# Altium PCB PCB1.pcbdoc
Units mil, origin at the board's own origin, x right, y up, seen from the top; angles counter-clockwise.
Board outline 2191.35 x 1279.37 mil, 4 copper layers (Top Layer, Inner1, Inner2, Bottom Layer), stack 38.584 mil thick; 62 components, 47 nets, 215 pads, 120 vias.
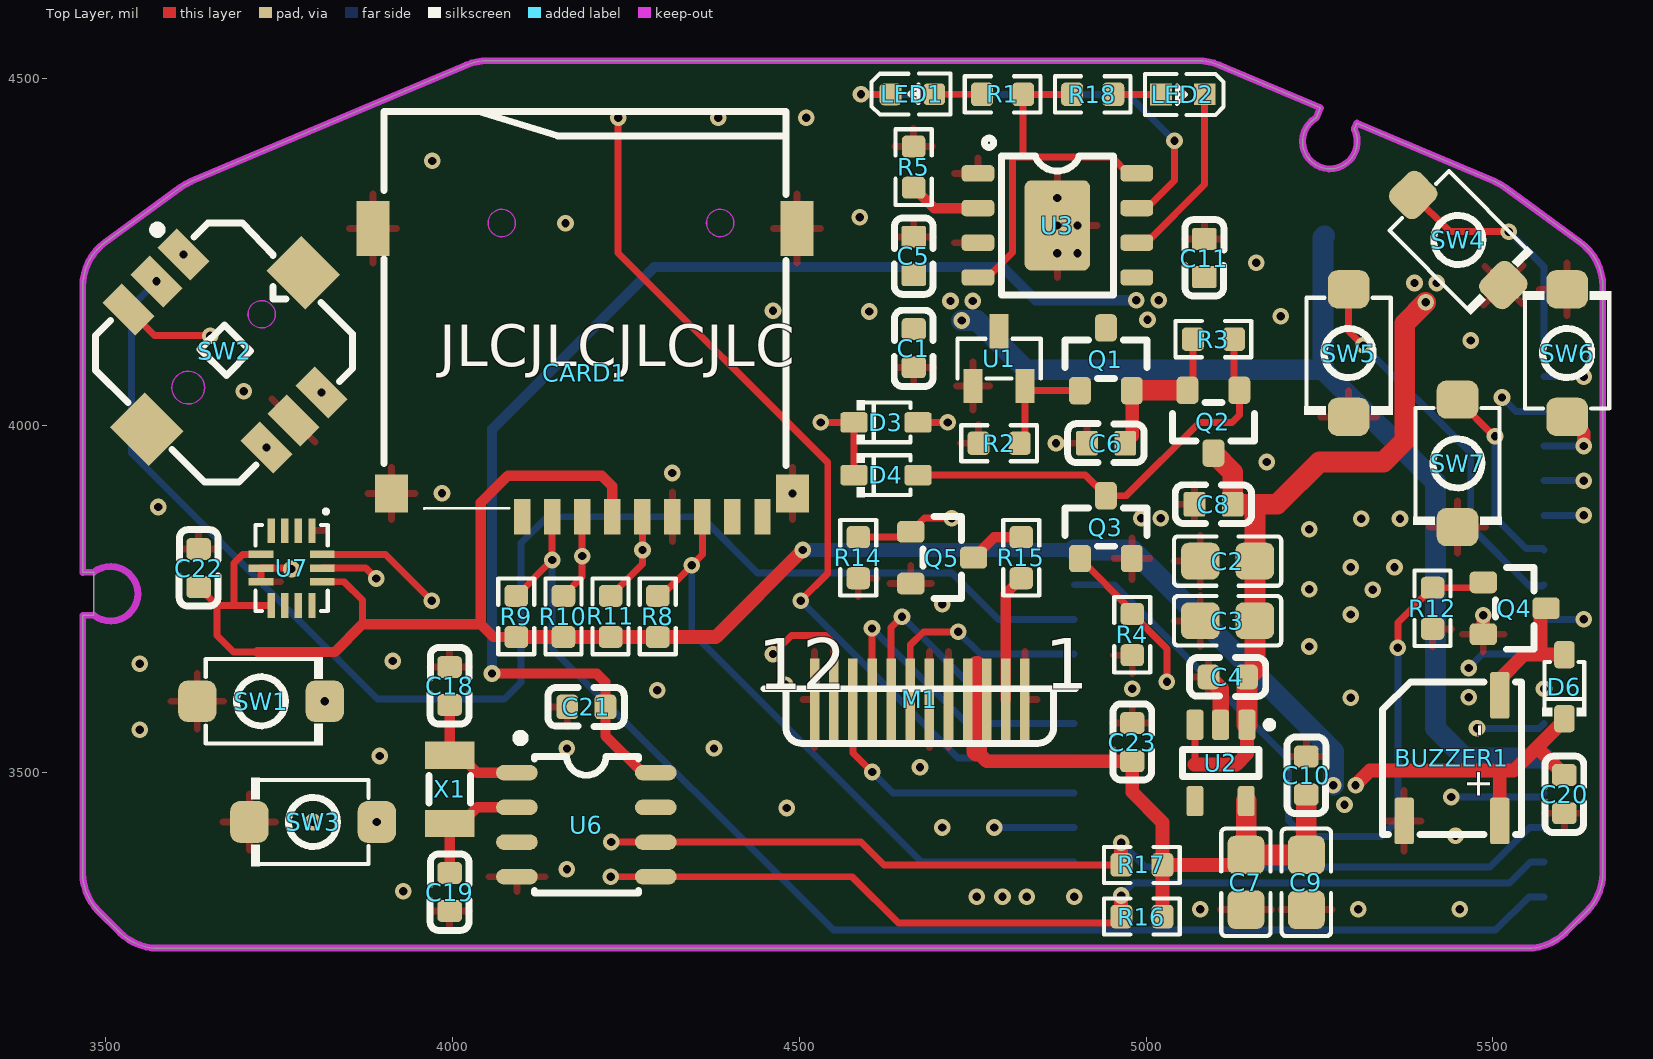
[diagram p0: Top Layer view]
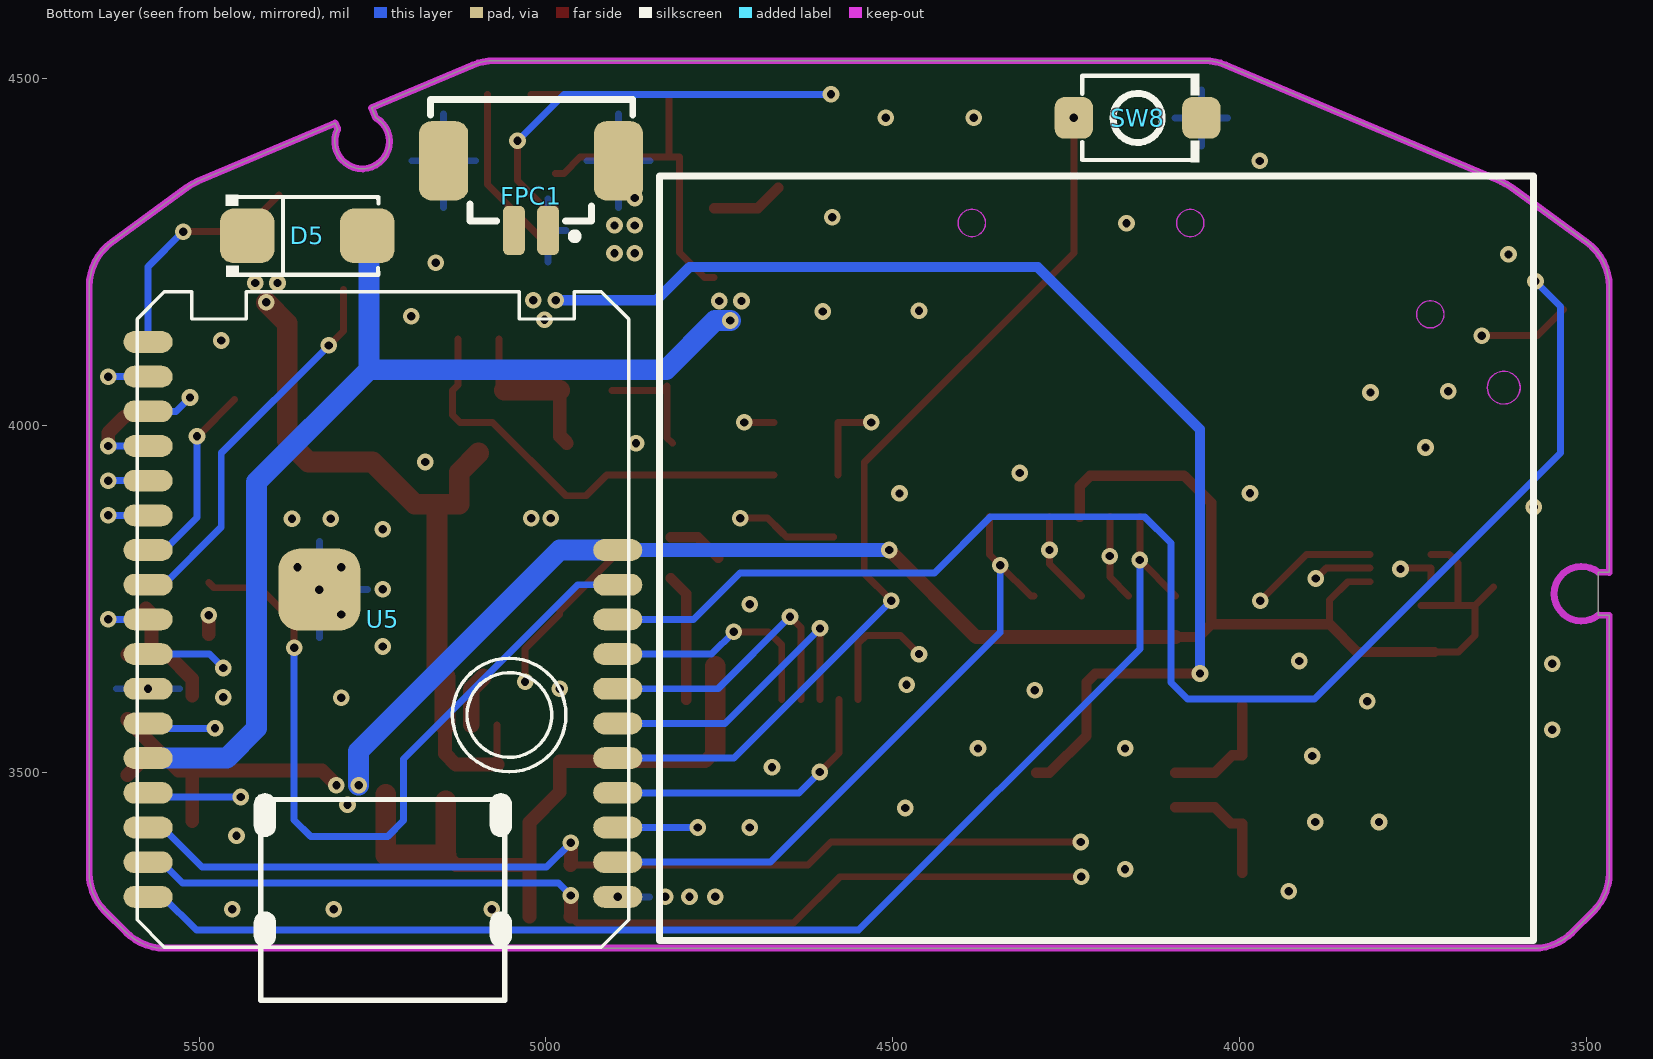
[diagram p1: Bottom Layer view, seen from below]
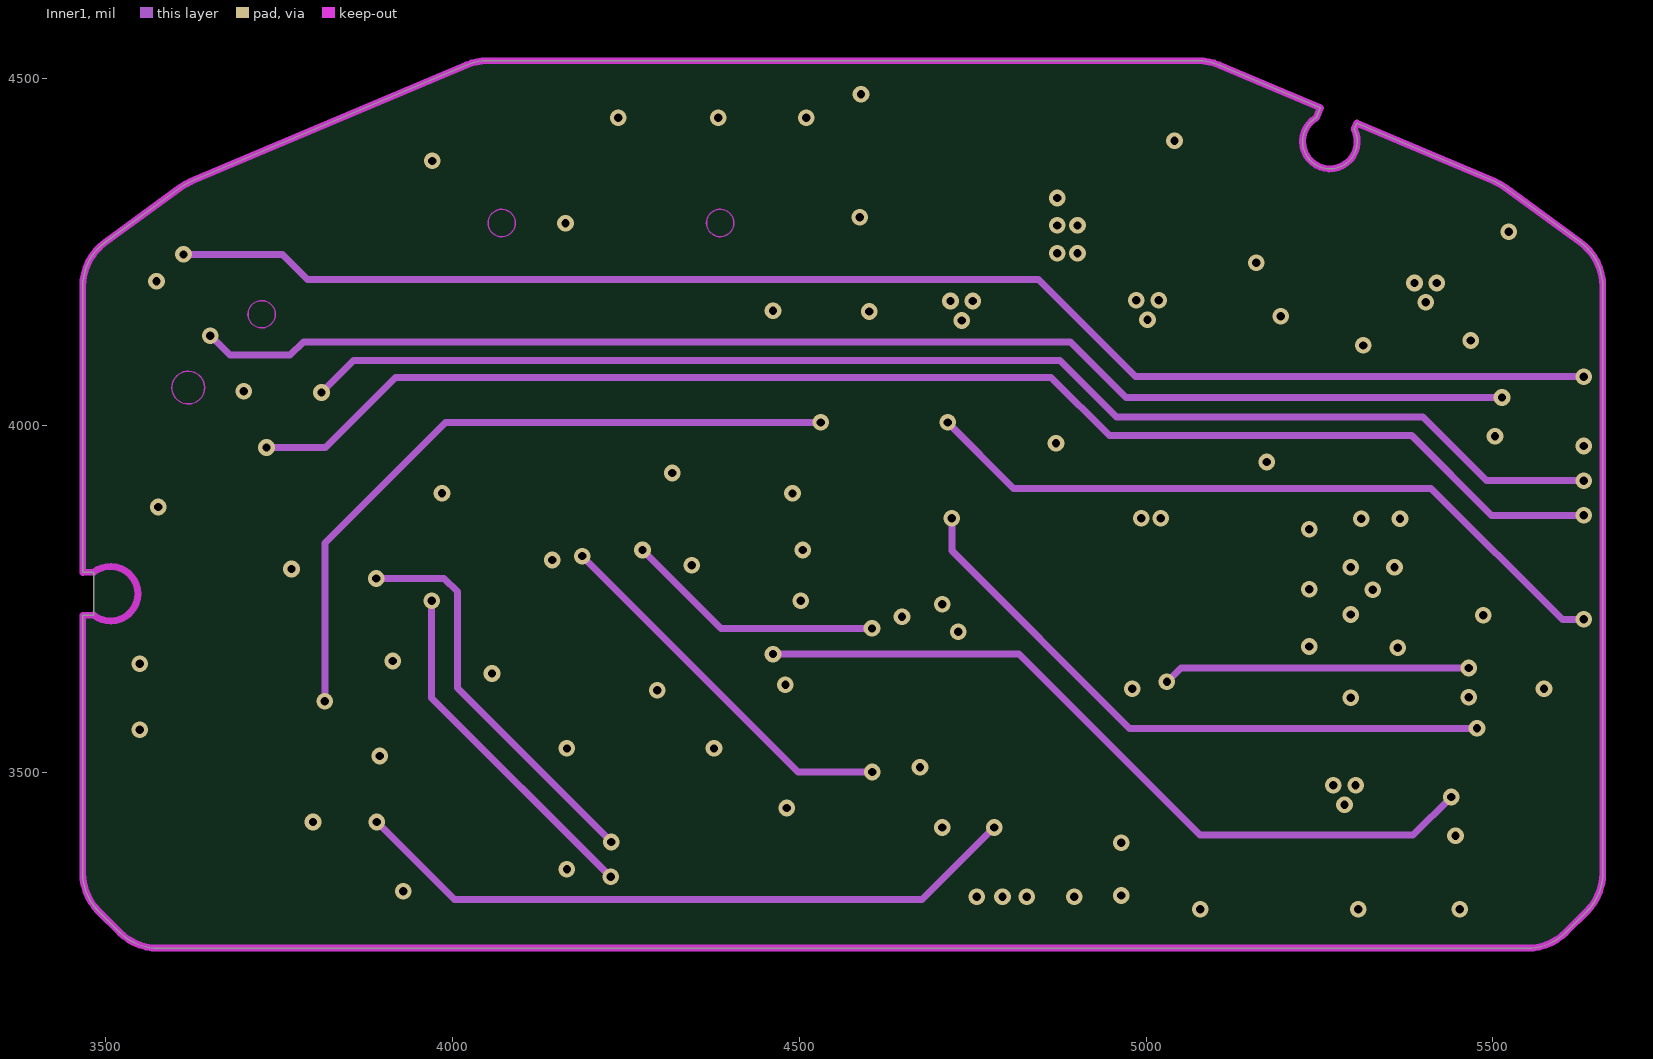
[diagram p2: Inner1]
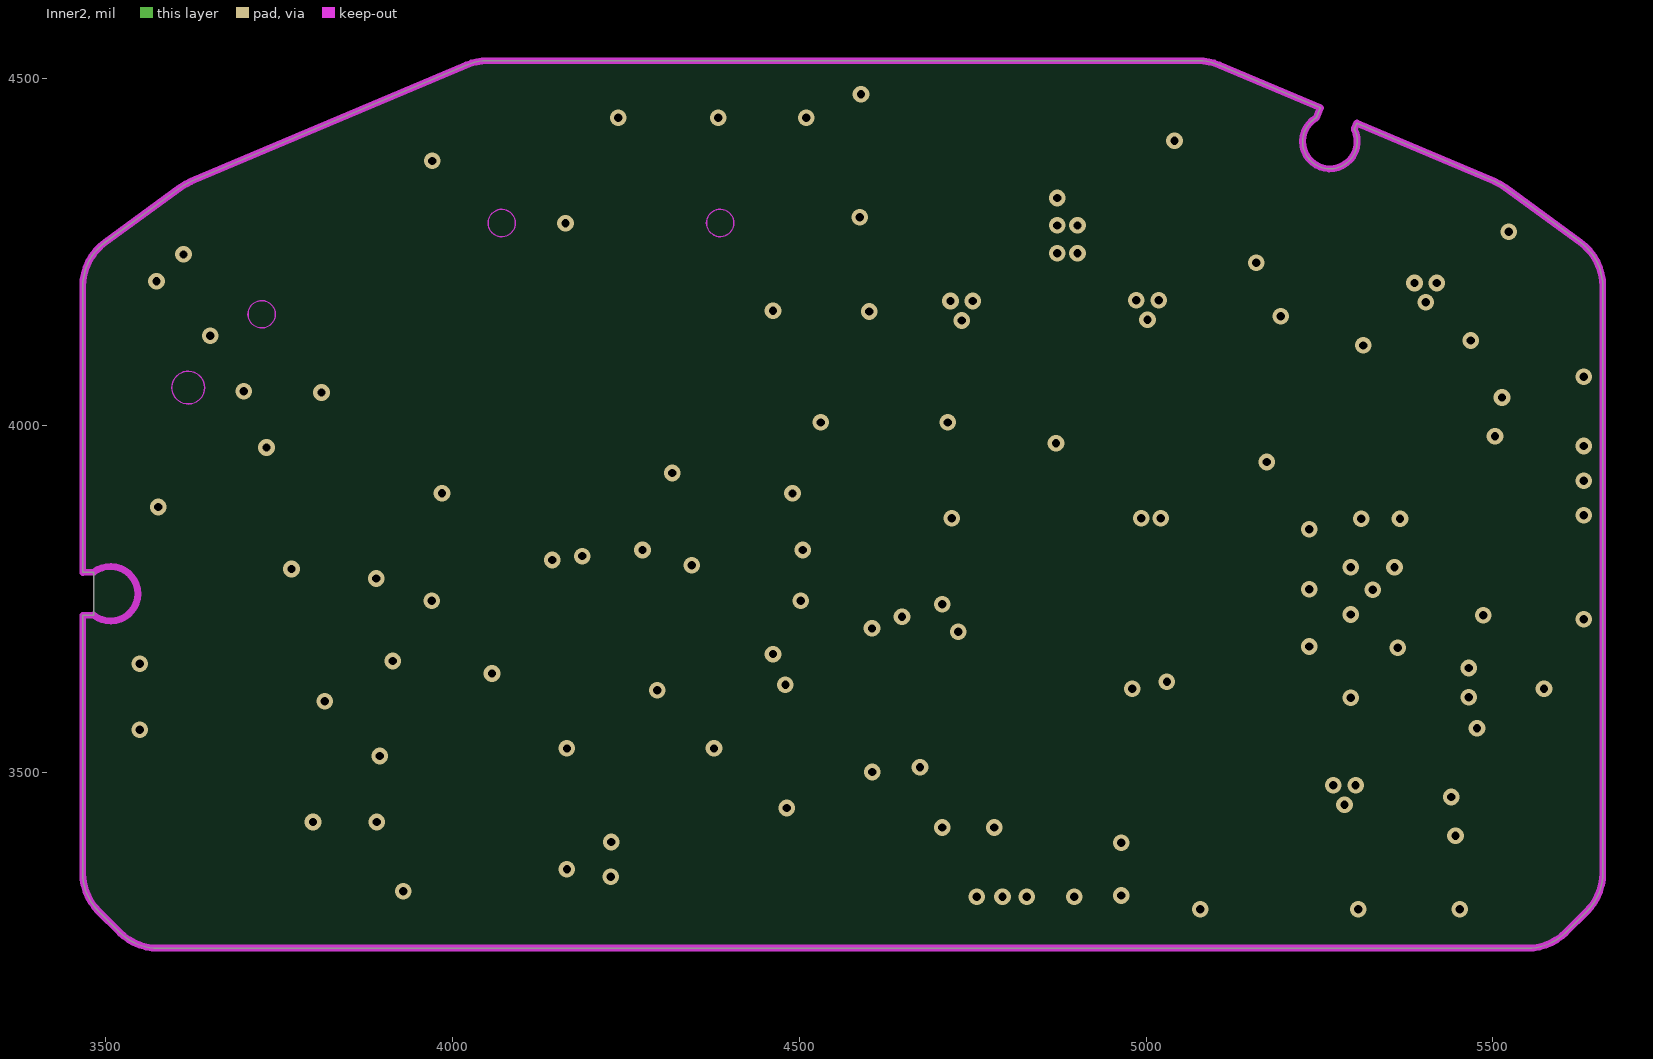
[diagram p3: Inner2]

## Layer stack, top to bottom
Top Solder Mask Layer: solder mask 0.394, Dk 0
Top Layer: signal copper 1.378
Dielectric1: surface 11.024, 7628 RC49% 8.6mil, Dk 0
Inner1: signal copper 1.378
Dielectric2: surface 11.024, 1.1mm H/HOZ 含铜, Dk 0
Inner2: signal copper 1.378
Dielectric3: surface 11.024, 7628 RC49% 8.6mil, Dk 0
Bottom Layer: signal copper 1.378
Bottom Solder Mask Layer: solder mask 0.394, Dk 0

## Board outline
3483,3788 3467,3787.83 3467,4200.07 cw(c3545.74,4200.07) 3499.36,4263.7 3607.66,4342.65 cw(c3654.04,4279.02) 3623.37,4351.54 4019.69,4519.16 cw(c4050.36,4446.63) 4050.36,4525.37 5074.98,4525.37 cw(c5074.98,4446.63) 5105.66,4519.16 5251.31,4457.55 5245,4443 ccw(c5264.96,4409.02) 5300.17,4426.72 5303.82,4435.35 5501.98,4351.54 cw(c5471.31,4279.02) 5517.69,4342.65 5625.99,4263.7 cw(c5579.61,4200.07) 5658.35,4200.07 5658.35,3354.62 cw(c5579.61,3354.62) 5635.29,3298.94 5605.41,3269.06 cw(c5549.73,3324.74) 5549.73,3246 3575.62,3246 cw(c3575.62,3324.74) 3519.94,3269.06 3490.06,3298.94 cw(c3545.74,3354.62) 3467,3354.62 3467,3725.92 3482.73,3726.12

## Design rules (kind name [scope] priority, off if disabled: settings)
BoardOutlineClearance copperThickness1oz [All] p0: genericclearance=10 ignorepadtopadclearanceinfootprint=FALSE except(0: Arc-SplitContinuation Track-SplitContinuation SMDPad-SplitContinuation THPad-SplitContinuation Via-SplitContinuation Fill-SplitContinuation Poly-SplitContinuation Region-SplitContinuation Text-SplitContinuation)
BoardOutlineClearance copperThickness2oz [All] p0: genericclearance=10 ignorepadtopadclearanceinfootprint=FALSE except(0: Arc-SplitContinuation Track-SplitContinuation SMDPad-SplitContinuation THPad-SplitContinuation Via-SplitContinuation Fill-SplitContinuation Poly-SplitContinuation Region-SplitContinuation Text-SplitContinuation)
BoardOutlineClearance Plane_innerPlane [All] p0: genericclearance=10 ignorepadtopadclearanceinfootprint=FALSE except(0: Arc-SplitContinuation Track-SplitContinuation SMDPad-SplitContinuation THPad-SplitContinuation Via-SplitContinuation Fill-SplitContinuation Poly-SplitContinuation Region-SplitContinuation Text-SplitContinuation)
BoardOutlineClearance Copper_copperRegion [All] p0: genericclearance=10 ignorepadtopadclearanceinfootprint=FALSE except(0: Arc-SplitContinuation Track-SplitContinuation SMDPad-SplitContinuation THPad-SplitContinuation Via-SplitContinuation Fill-SplitContinuation Poly-SplitContinuation Region-SplitContinuation Text-SplitContinuation)
BoardOutlineClearance Copper_copperAll [All] p0: genericclearance=10 ignorepadtopadclearanceinfootprint=FALSE except(0: Arc-SplitContinuation Track-SplitContinuation SMDPad-SplitContinuation THPad-SplitContinuation Via-SplitContinuation Fill-SplitContinuation Poly-SplitContinuation Region-SplitContinuation Text-SplitContinuation)
BoardOutlineClearance otherClearance [All] p0: genericclearance=10 ignorepadtopadclearanceinfootprint=FALSE except(0: Arc-SplitContinuation Track-SplitContinuation SMDPad-SplitContinuation THPad-SplitContinuation Via-SplitContinuation Fill-SplitContinuation Poly-SplitContinuation Region-SplitContinuation Text-SplitContinuation)
Clearance copperThickness1oz [All] p1: gap=7 ignorepadtopadclearanceinfootprint=FALSE
Clearance copperThickness2oz [All] p1: gap=7 ignorepadtopadclearanceinfootprint=FALSE
Clearance Plane_innerPlane [All] p1: gap=7 ignorepadtopadclearanceinfootprint=FALSE
Clearance Copper_copperRegion [All] p1: gap=7 ignorepadtopadclearanceinfootprint=FALSE
Clearance Copper_copperAll [All] p1: gap=7 ignorepadtopadclearanceinfootprint=FALSE
Clearance otherClearance [All] p1: gap=7 ignorepadtopadclearanceinfootprint=FALSE
DiffPairsRouting differentialPair [All] p1: maxuncoupledlength=10 minlimit=6 maxlimit=Infinity mostfreqgap=6 toplayer_minwidth=5 toplayer_prefwidth=10 toplayer_maxwidth=100 bottomlayer_minwidth=5 bottomlayer_prefwidth=10 bottomlayer_maxwidth=100 midlayer1_minwidth=5 midlayer1_prefwidth=10 midlayer1_maxwidth=100 midlayer2_minwidth=5 midlayer2_prefwidth=10 midlayer2_maxwidth=100
PasteMaskExpansion pasteMaskExpansion [All] p1: expansion=0
PlaneConnect innerPlane [All] p1: planeconnectstyle=Relief reliefexpansion=20 reliefentries=4 reliefconductorwidth=10 reliefairgap=10
PolygonConnect copperRegion [All] p1: connectstyle=Relief reliefentries=4 reliefconductorwidth=10 polygonreliefangle="90 Angle" airgapwidth=10
PolygonConnect copperAll [All] p1: connectstyle=Direct reliefentries=4 reliefconductorwidth=10 polygonreliefangle="90 Angle" airgapwidth=10
RoutingVias viaSize [All] p1: viastyle="Through Hole" holewidth=12 minholewidth=11.8 maxholewidth=248 width=12 minwidth=11.8 maxwidth=248
SolderMaskExpansion solderMaskExpansion [All] p1: useseparateexpansions=TRUE expansion=2 expansionbottom=2
Width copperThickness1oz [All] p1: maxlimit=100 minlimit=5 preferedwidth=10
Width copperThickness2oz [All] p1: maxlimit=100 minlimit=8 preferedwidth=10

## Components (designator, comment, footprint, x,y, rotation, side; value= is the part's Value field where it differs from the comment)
BUZZER1 "" BUZ-SMD_L5.0-W5.5-P4.60 5441,3520 r90 top
C1 "" C0603#1 4665.05,4111 r90 top
C2 "" C0805 5117.44,3804 r0 top
C3 "" C0805 5117.44,3718 r0 top
C4 "" C0603#1 5117.75,3637 r0 top
C5 "" C0603#2 4665.05,4244 r90 top
C6 "" C0603#2 4942.31,3974 r0 top
C7 "" C0805 5144,3341 r90 top
C8 "" C0603#2 5097.31,3886 r0 top
C9 "" C0805 5231,3341 r90 top
C10 "" C0603#1 5231,3494.97 r270 top
C11 "" C0603#2 5083.89,4241 r270 top
C18 "" C0603#1 3995.79,3624 r270 top
C19 "" C0603#1 3996,3327 r90 top
C20 "" C0603#1 5603,3468.11 r90 top
C21 "" C0603#1 4193,3593.77 r0 top
C22 "" C0603#1 3634,3794 r270 top
C23 "" C0603#1 4980,3543 r270 top
CARD1 "" TF-SMD_TF-01A 4191,4075.88 r180 top
D3 "" SOD-323_L1.8-W1.3-LS2.5-RD#1 4625,4004 r0 top
D4 "" SOD-323_L1.8-W1.3-LS2.5-RD#1 4625,3928 r0 top
D5 "" SMA_L4.3-W2.6-LS5.2-RD 5344,4273 r180 bottom
D6 "" SOD-323_L1.8-W1.3-LS2.5-RD#2 5603,3623 r90 top
FPC1 "" CONN-SMD_2P-P1.25_DEALON_1.25-2PWB 5021.4,4331 r0 bottom locked
LED1 "" LED0603-RD-YELLOW 4663,4477 r0 top
LED2 "" LED0603-RD 5053,4477 r180 top
M1 "" 1.3寸TFT240_240 4043.84,3183.09 r0 top locked
Q1 "" SOT-23_L2.9-W1.3-P1.90-LS2.4-BR 4942,4095 r270 top
Q2 "" SOT-23_L2.9-W1.3-P1.90-LS2.4-BR 5097,4005.01 r90 top
Q3 "" SOT-23-3_L2.9-W1.6-P1.90-LS2.8-BR 4942,3853 r270 top
Q4 "" SOT-23-3_L2.9-W1.6-P1.90-LS2.8-BR 5531.35,3736 r180 top
Q5 "" SOT-23-3_L2.9-W1.6-P1.90-LS2.8-BR 4706,3809 r180 top
R1 "" R0603 4793,4477 r180 top
R2 "" R0603 4788,3974 r0 top
R3 "" R0603 5097,4124 r180 top
R4 "" R0603 4980,3698 r90 top
R5 "" R0603 4664.95,4372 r270 top
R8 "" R0603 4296,3724.26 r270 top
R9 "" R0603 4092,3724.26 r270 top
R10 "" R0603 4160,3724.26 r270 top
R11 "" R0603 4228,3724.26 r270 top
R12 "" R0603 5413,3736 r270 top
R14 "" R0603 4585,3809 r270 top
R15 "" R0603 4820,3809 r270 top
R16 "" R0603 4994,3291.57 r0 top
R17 "" R0603 4994,3366 r0 top
R18 "" R0603 4923,4477 r0 top
SW1 "" SW-SMD_L3.9-W3.0-P4.45 3724,3602 r0 top
SW2 "" SW-SMD_TM-4175-B-X 3672,4107 r315 top locked
SW3 "" SW-SMD_L3.9-W3.0-P4.45 3799,3428 r180 top
SW4 "" SW-SMD_L3.9-W3.0-P4.45 5450,4267 r315 top
SW5 "" SW-SMD_L3.9-W3.0-P4.45 5292,4104 r270 top
SW6 "" SW-SMD_L3.9-W3.0-P4.45 5607,4104 r90 top
SW7 "" SW-SMD_L3.9-W3.0-P4.45 5449,3945 r270 top
SW8 "" SW-SMD_L3.9-W3.0-P4.45 4147,4443 r180 bottom
U1 "" SOT-23-3_L2.9-W1.3-P1.90-LS2.4-BR 4788,4095.98 r270 top
U2 "" SOT-25-5_L3.0-W1.8-P0.95-LS3.0-BR 5107.87,3513 r90 top
U3 "" ESOP-8_L4.9-W3.9-P1.27-LS6.0-BL-EP 4872,4288 r270 top
U5 "" STAMP-S3-PIN-SMD 5235,3720 r180 bottom locked
U6 "" SOIC-8_L5.0-W4.0-P1.27-LS6.0-BL 4193,3424 r270 top
U7 "" LGA-14_L3.0-W2.5-P0.50-BR 3768,3794 r90 top
X1 "" FC-135R_L3.2-W1.5 3996,3475 r270 top

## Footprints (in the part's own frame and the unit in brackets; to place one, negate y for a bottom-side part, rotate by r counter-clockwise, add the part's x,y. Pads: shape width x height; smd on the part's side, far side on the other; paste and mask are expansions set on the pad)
1.3寸TFT240_240 [mm]
  rect 0.35x3 smd: 1(19.85,10.7) 2(19.15,10.7) 3(18.45,10.7) 4(17.75,10.7) 5(17.05,10.7) 6(16.35,10.7) 7(15.65,10.7) 8(14.95,10.7) 9(14.25,10.7) 10(13.55,10.7) 11(12.85,10.7) 12(12.15,10.7)
  silkscreen extent 10.3,9.1 21.7,11.1
BUZ-SMD_L5.0-W5.5-P4.60 [mm]
  rrect20% 1.7x0.7 smd: 1(-2.3,-1.75) 2(2.3,-1.75) 3(-2.3,1.75)
  silkscreen extent -2.79,-2.54 2.79,2.54
C0603#1 [mm]
  rrect40% 0.8x0.9 smd: 1(-0.7,0) 2(0.7,0)
  silkscreen extent -1.41,-0.71 1.39,0.72
C0603#2 [mm]
  rrect20% 0.8x0.9 smd: 1(-0.7,0) 2(0.7,0)
  silkscreen extent -1.41,-0.71 1.39,0.72
C0805 [mm]
  rrect40% 1.41x1.35 smd: 1(-1,0) 2(1,0)
  silkscreen extent -1.96,-0.9 1.96,0.9
CONN-SMD_2P-P1.25_DEALON_1.25-2PWB [mm]
  rrect50% 0.8x1.8 smd: 1(-0.625,1.275) 2(0.625,1.275)
  rrect50% 1.8x2.9 smd: 3(-3.2,-1.275) 4(3.2,-1.275)
  silkscreen extent -3.73,-3.52 3.67,1.62
ESOP-8_L4.9-W3.9-P1.27-LS6.0-BL-EP [mm]
  rrect50% 0.6x1.2 smd: 1(-1.905,-2.908) 2(-0.635,-2.908) 3(0.635,-2.908) 4(1.905,-2.908) 5(1.905,2.908) 6(0.635,2.908) 7(-0.635,2.908) 8(-1.905,2.908)
  rrect20% 3.3x2.4 smd: 9(0,0)
  silkscreen extent -3.2,-2.67 2.55,2.05
FC-135R_L3.2-W1.5 [mm]
  rect 1x1.8 smd: 1(-1.25,0) 2(1.25,0)
  silkscreen extent -0.51,-0.76 0.51,0.76
LED0603-RD [mm]
  rect 0.8x0.8 smd: 1(-0.799,-0.003) 2(0.799,0.003)
  silkscreen extent -1.49,-0.75 1.39,0.76
LED0603-RD-YELLOW [mm]
  rrect40% 0.8x0.8 smd: 1(-0.799,-0.003) 2(0.799,0.003)
  silkscreen extent -1.49,-0.75 1.39,0.76
LGA-14_L3.0-W2.5-P0.50-BR [mm]
  rect 0.9x0.27 smd: 1(1.37,-0.75) 2(1.37,-0.25) 3(1.37,0.25) 4(1.37,0.75) 8(-1.37,0.75) 9(-1.37,0.25) 10(-1.37,-0.25) 11(-1.37,-0.75)
  rect 0.27x0.9 smd: 5(0.5,1.12) 6(0,1.12) 7(-0.5,1.12) 12(-0.5,-1.12) 13(0,-1.12) 14(0.5,-1.12)
  silkscreen extent -1.58,-1.33 2.14,1.33
R0603 [mil]
  rrect40% 31.75x34.02 smd: 1(-29.66,0) 2(29.66,0)
  silkscreen extent -55,-26 55,26
SMA_L4.3-W2.6-LS5.2-RD [mm]
  rrect50% 2x2 smd: 1(-2.2,0) 2(2.2,0)
  silkscreen extent -2.98,-1.5 2.6,1.5
SOD-323_L1.8-W1.3-LS2.5-RD#1 [mm]
  rrect30% 1x0.75 smd: 1(-1.173,0) 2(1.173,0)
  silkscreen extent -1.08,-0.8 0.9,0.8
SOD-323_L1.8-W1.3-LS2.5-RD#2 [mm]
  rrect40% 1x0.75 smd: 1(-1.173,0) 2(1.173,0)
  silkscreen extent -1.08,-0.8 0.9,0.8
SOIC-8_L5.0-W4.0-P1.27-LS6.0-BL [mil]
  oval 22.38x60 smd: 1(-75,-100) 2(-25,-100) 3(25,-100) 4(75,-100) 5(75,100) 6(25,100) 7(-25,100) 8(-75,100)
  silkscreen extent -131,-101 98,75
SOT-23-3_L2.9-W1.3-P1.90-LS2.4-BR [mm]
  rect 1.25x0.7 smd: 1(1,-0.95) 2(1,0.95) 3(-1,0)
  silkscreen extent -0.73,-1.53 0.73,1.53
SOT-23-3_L2.9-W1.6-P1.90-LS2.8-BR [mm]
  rrect40% 1x0.8 smd: 1(1.15,-0.95) 2(1.15,0.95) 3(-1.15,0)
  silkscreen extent -0.7,-1.5 0.7,1.5
SOT-23_L2.9-W1.3-P1.90-LS2.4-BR [mm]
  rrect40% 1x0.8 smd: 1(1.15,-0.95) 2(1.15,0.95) 3(-1.15,0)
  silkscreen extent -0.7,-1.5 0.7,1.5
SOT-25-5_L3.0-W1.8-P0.95-LS3.0-BR [mil]
  rrect30% 43.5x24.5 smd: 1(55,-37.5) 2(55,0.5) 3(55,37.5) 4(-55,37.5) 5(-55,-36.5)
  silkscreen extent -20,-75 60,56
STAMP-S3-PIN-SMD [mm]
  oval 1.8x0.8 smd: 1(-8.6,10.16) 2(-8.6,8.89) 3(-8.6,7.62) 4(-8.6,6.35) 5(-8.6,5.08) 6(-8.6,3.81) 7(-8.6,2.54) 8(-8.6,1.27) 9(-8.6,0) 10(-8.6,-1.27) 11(-8.6,-2.54) 12(-8.6,-3.81) 13(-8.6,-5.08) 14(-8.6,-6.35) 15(-8.6,-7.62) 16(-8.6,-8.89) 17(-8.6,-10.16) 18(8.6,-10.16) 19(8.6,-8.89) 20(8.6,-7.62) 21(8.6,-6.35) 22(8.6,-5.08) 23(8.6,-3.81) 24(8.6,-2.54) 25(8.6,-1.27) 26(8.6,0) 27(8.6,1.27) 28(8.6,2.54)
  rrect50% 3x3 smd: 31(-2.328,1.088)
  silkscreen extent -9,-13.95 9,12
SW-SMD_L3.9-W3.0-P4.45 [mil]
  rrect50% 55x60 smd: 1(-91.93,0) 2(91.93,0)
  silkscreen extent -80,-64 89,64
SW-SMD_TM-4175-B-X [mm]
  rect 1.7x1 smd: 1(-3.575,1.425) 2(-3.575,0.028) 3(-3.575,-1.425) 4(3.575,1.425) 5(3.575,-0.028) 6(3.575,-1.425)
  rect 2x1.8 smd: 7(0,4.05) 7(0,-4.05)
  Board Outline Layer circle w0.003: c0,1.9 r0.5
  Board Outline Layer circle w0.003: c0,-1.9 r0.6
  Board Outline Layer region: 0.354,2.254 0.472,2.065 0.497,1.844 0.423,1.634 0.266,1.477 0.056,1.403 -0.165,1.428 -0.354,1.546 -0.354,1.546 -0.472,1.735 -0.497,1.956 -0.423,2.166 -0.266,2.323 -0.056,2.397 0.165,2.372 0.354,2.254
  Board Outline Layer region: 0.354,2.254 0.472,2.065 0.497,1.844 0.423,1.634 0.266,1.477 0.056,1.403 -0.165,1.428 -0.354,1.546 -0.354,1.546 -0.472,1.735 -0.497,1.956 -0.423,2.166 -0.266,2.323 -0.056,2.397 0.165,2.372 0.354,2.254
  Board Outline Layer region: 0.424,-1.476 0.566,-1.702 0.596,-1.967 0.508,-2.219 0.319,-2.408 0.067,-2.496 -0.198,-2.466 -0.424,-2.324 -0.424,-2.324 -0.566,-2.098 -0.596,-1.833 -0.508,-1.581 -0.319,-1.392 -0.067,-1.304 0.198,-1.334 0.424,-1.476
  Board Outline Layer region: 0.424,-1.476 0.566,-1.702 0.596,-1.967 0.508,-2.219 0.319,-2.408 0.067,-2.496 -0.198,-2.466 -0.424,-2.324 -0.424,-2.324 -0.566,-2.098 -0.596,-1.833 -0.508,-1.581 -0.319,-1.392 -0.067,-1.304 0.198,-1.334 0.424,-1.476
  silkscreen extent -5.04,-3.93 3.76,3.76
TF-SMD_TF-01A [mm]
  rect 0.6x1.3 smd: 1(2.301,5.276) 2(1.201,5.276) 3(0.101,5.276) 4(-0.999,5.276) 5(-2.099,5.276) 6(-3.199,5.276) 7(-4.299,5.276) 8(-5.399,5.276) 9(-6.499,5.276)
  rect 1.2x1.4 smd: 10(-7.599,4.426) 13(7.081,4.426)
  rect 1.2x2 smd: 11(-7.76,-5.276) 12(7.76,-5.276)
  Board Outline Layer circle w0.003: c-4.95,-5.478 r0.5
  Board Outline Layer circle w0.003: c3.05,-5.475 r0.5
  Board Outline Layer region: -5.45,-5.478 -5.4,-5.261 -5.262,-5.087 -5.061,-4.991 -4.839,-4.991 -4.638,-5.087 -4.5,-5.261 -4.45,-5.478 -4.45,-5.478 -4.5,-5.695 -4.638,-5.869 -4.839,-5.965 -5.061,-5.965 -5.262,-5.869 -5.4,-5.695 -5.45,-5.478
  Board Outline Layer region: -5.45,-5.478 -5.4,-5.261 -5.262,-5.087 -5.061,-4.991 -4.839,-4.991 -4.638,-5.087 -4.5,-5.261 -4.45,-5.478 -4.45,-5.478 -4.5,-5.695 -4.638,-5.869 -4.839,-5.965 -5.061,-5.965 -5.262,-5.869 -5.4,-5.695 -5.45,-5.478
  Board Outline Layer region: 2.55,-5.475 2.6,-5.258 2.738,-5.085 2.939,-4.988 3.161,-4.988 3.362,-5.085 3.5,-5.258 3.55,-5.475 3.55,-5.475 3.5,-5.692 3.362,-5.866 3.161,-5.963 2.939,-5.963 2.738,-5.866 2.6,-5.692 2.55,-5.475
  Board Outline Layer region: 2.55,-5.475 2.6,-5.258 2.738,-5.085 2.939,-4.988 3.161,-4.988 3.362,-5.085 3.5,-5.258 3.55,-5.475 3.55,-5.475 3.5,-5.692 3.362,-5.866 3.161,-5.963 2.939,-5.963 2.738,-5.866 2.6,-5.692 2.55,-5.475
  silkscreen extent -7.37,-9.56 7.37,4.97

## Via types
v1: diameter 24, hole 12, Top Layer to Bottom Layer, 108 vias
v2: diameter 24.02, hole 12.01, Top Layer to Bottom Layer, 12 vias

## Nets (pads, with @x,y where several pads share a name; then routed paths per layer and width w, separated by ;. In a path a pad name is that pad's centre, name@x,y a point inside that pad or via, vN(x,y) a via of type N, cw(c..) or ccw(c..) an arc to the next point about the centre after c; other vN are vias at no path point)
$1N2328: R5.2 U3.2 | length 104.7
  Top Layer w15: R5.2 4694.29,4313 U3.2
$1N2338: Q1.1 R2.2 U1.2 | length 167.9
  Top Layer w10: R2.2 4825.4,3981.74 U1.2 4832.29,4049.72 Q1.1
$1N2343: C6.2 Q1.2 Q2.2 R3.2 | length 237.8
  Top Layer w10: Q1.2 Q1.2@4979.96,4050.28 ; Q2.2 5067.34,4058.03 R3.2
  Top Layer w20: C6.2 4979.96,3984.1 Q1.2@4979.96,4050.28
  Top Layer w30: Q1.2@4979.96,4050.28 Q2.2
$1N2351: D4.2 Q2.1 Q3.3 R3.1 | length 636.5
  Top Layer w10: D4.2 4912.28,3928 Q3.3 4971.28,3898.28 5077,4004 5124,4004 5134.4,4014.4 Q2.1 5126.66,4058.03 R3.1
$1N2352: D3.1 D4.1 SW1.2 | length 1138.9
  Top Layer w10: v1(4531,4004) D3.1 D4.1
  Inner1 w10: v1(3815.93,3602) 3815.93,3829.93 3990,4004 v1(4531,4004)
$1N2361: LED1.2 R1.2 | length 68.9
  Top Layer w10: LED1.2 4763.2,4477.14 R1.2
$1N5094: BUZZER1.2 D6.2 Q4.3 | length 201.3
  Top Layer w20: BUZZER1.2 5509.9,3633.89 5545.16,3669.16 5568.51,3669.16 ; Q4.3 5568.51,3727.88 5568.51,3669.16 ; D6.2 5568.51,3669.16
$1N6154: C19.2 U6.2 X1.2 | length 177.8
  Top Layer w15: C19.2 X1.2 4012.78,3425.78 4036,3449 U6.2
$1N6155: C18.2 U6.1 X1.1 | length 179.8
  Top Layer w15: C18.2 3995.99,3596.23 X1.1 4010.78,3524.22 4036,3499 U6.1
$1N15050: LED1.1 U3.7 | length 650.4
  Top Layer w10: v1(4589,4477) 4631.39,4477 LED1.1 ; U3.7 5001,4313 5041,4353 v1(5041,4410)
  Bottom Layer w10: v1(4589,4477) 4974,4477 v1(5041,4410)
$1N15134: LED2.2 R18.2 | length 68.9
  Top Layer w10: R18.2 5021.39,4477 LED2.2
$1N15243: LED2.1 U3.6 | length 263
  Top Layer w10: U3.6 5000.64,4263 5084.48,4346.83 LED2.1
$1N15373: Q5.3 R15.1 | length 81
  Top Layer w15: Q5.3 4780.94,3838.66 R15.1
BUS_I2C_CLK: R17.1 U5.15 U6.6 U7.13 | length 2090.8
  Top Layer w10: U7.13 3875.01,3793.99 v1(3890,3779) ; v1(4229,3399) U6.6 4589,3399 4622,3366 R17.1
  Top Layer w20: v1(4964,3398) 4964,3366.34 R17.1
  Inner1 w10: v1(3890,3779) 3988,3779 4007,3760 4007,3621 v1(4229,3399)
  Bottom Layer w10: v1(4964,3398) 4999,3363 5496,3363 5553,3420 U5.15
BUS_I2C_SDA: R16.1 U5.16 U6.5 U7.14 | length 2118.5
  Top Layer w10: U7.14 3903.32,3813.68 v1(3970,3747) ; v1(4228,3349) U6.5 4576,3349 4643,3282 4954.77,3282 R16.1
  Top Layer w20: v1(4964,3322) 4964,3291.91 R16.1
  Inner1 w10: v1(3970,3747) 3970,3607 v1(4228,3349)
  Bottom Layer w10: v1(4964,3322) 4982,3340 5524,3340 5554,3370 U5.16
BUS_SPI_CLK: CARD1.5 M1.9 R11.1 U5.23 | length 962.1
  Top Layer w10: R11.1 4274,3799.92 v1(4274,3820) 4274,3867.82 CARD1.5 ; M1.9 v1(4604.87,3707)
  Inner1 w10: v1(4274,3820) 4387,3707 v1(4604.87,3707)
  Bottom Layer w10: v1(4604.87,3707) 4741.87,3570 U5.23
BUS_SPI_CS_LCD: M1.8 U5.24 | length 417.6
  Top Layer w10: M1.8 4632.43,3708.43 v1(4648,3724)
  Bottom Layer w10: v1(4648,3724) 4752,3620 U5.24
BUS_SPI_CS_SD: CARD1.2 R9.1 U5.17 | length 1881.7
  Top Layer w10: R9.1 v1(4143.73,3805.65) CARD1.2
  Bottom Layer w10: v1(4143.73,3805.65) 4143.73,3677.27 4549,3272 5504,3272 5552,3320 U5.17
BUS_SPI_MISO: CARD1.7 R8.1 U5.19 | length 929.3
  Top Layer w10: R8.1 4300.92,3753.92 v1(4345,3798) 4360.27,3813.27 CARD1.7
  Bottom Layer w10: v1(4345,3798) 4345,3701 4676,3370 U5.19
BUS_SPI_MOSI: CARD1.3 M1.10 R10.1 U5.21 | length 1092
  Top Layer w10: R10.1 4187.04,3780.96 v1(4187.04,3811.29) CARD1.3 ; M1.10 4577.31,3527.69 v1(4605,3500)
  Inner1 w10: v1(4187.04,3811.29) 4498.33,3500 v1(4605,3500)
  Bottom Layer w10: v1(4605,3500) 4635,3470 U5.21
ESP_EN: SW8.1 U5.22 | length 1325.7
  Top Layer w10: v1(4238.93,4443) 4238.93,4248.07 4541,3946 4541,3786 v1(4502,3747)
  Bottom Layer w10: v1(4502,3747) 4729,3520 U5.22
GND: BUZZER1.3 C1.1 C2.1 C3.1 C4.1 C5.2 C6.1 C7.1 C8.1 C9.1 C10.1 C11.1 C18.1 C19.1 C20.1 C21.1 C22.1 C23.1 CARD1.6 CARD1.10 CARD1.11 CARD1.12 CARD1.13 FPC1.1 FPC1.3 FPC1.4 M1.1 M1.5 M1.6 M1.12 Q3.2 Q4.2 Q5.2 R2.1 R4.1 R5.1 R12.2 R14.2 SW1.1 SW2.5 SW3.2 SW4.2 SW5.2 SW6.2 SW7.2 SW8.2 U1.1 U2.2 U3.1 U3.3 U3.9 U5.11 U5.18 U5.31 U6.4 U7.1 U7.6 U7.7 | length 167.9
  Top Layer w10: U7.7 U7.6 3766.67,3793.99 v1(3768,3792.67)
  Top Layer w20: v1(5486,3726) 5486.07,3725.93 Q4.2
  Top Layer w24: C4.1 5107.37,3619.82 U2.2
  other v1: 5078,3302 5306,3302 5452,3302 4756,3320 4793,3320 4828,3320 4896.42,3320 3929,3328 4165,3360 5446,3408 4706,3420 3799,3428 4482,3448 4674,3507 3895,3523 4165,3534 4377,3534 3549,3561 5295,3607 5465,3608 4295,3618 4980,3620 5573.58,3620 4480,3626 3549,3656 3914,3660 5235,3680.99 5295,3727 4706,3742 5235,3763.46 5326.66,3762.84 5295,3795 5358,3795 5235,3849.85 5310,3865 5366,3865 4993,3866 5021,3866 3576,3882 3985,3902 4490.19,3901.64 4317,3931 5174,3947 4870,3974 3699,4049 5468,4122 5194,4157 4601,4164 4462,4165 5159,4234 4872,4248 4901,4248 4872,4288 4901,4288 4163,4291 4587,4300 4872,4327.55 3971,4381 4383,4443 4510,4443
GPIO0: SW3.1 U5.20 | length 1095
  Inner1 w10: v1(3890.93,3428) 4002.93,3316 4677,3316 v1(4781,3420)
  Bottom Layer w10: v1(4781,3420) U5.20
GPIO1: SW4.1 U5.1 | length 339.9
  Top Layer w10: SW4.1 5438,4279 v1(5523,4279)
  Bottom Layer w10: v1(5523,4279) 5573.58,4228.42 U5.1
GPIO2: SW2.1 U5.2 | length 2149.3
  Inner1 w10: v1(3612.14,4246.2) 3754.8,4246.2 3791,4210 4845,4210 4985,4070 v1(5631,4070)
  Bottom Layer w10: U5.2 v1(5631,4070)
GPIO3: SW2.3 U5.3 | length 2117.3
  Top Layer w10: SW2.3 3570.66,4129 v1(3651,4129)
  Inner1 w10: v1(3651,4129) 3679,4101 3766,4101 3785,4120 4891,4120 4971,4040 v1(5513,4040)
  Bottom Layer w10: v1(5513,4040) 5533,4020 U5.3
GPIO4: SW6.1 U5.4 | length 110
  Top Layer w20: SW6.1 5607.93,4012.07 5631,3989 v1(5631,3970)
  Bottom Layer w10: U5.4 v1(5631,3970)
GPIO5: SW2.4 U5.5 | length 1967.9
  Inner1 w10: v1(3811.2,4047.14) 3857.05,4093 4876,4093 4957,4012 5399,4012 5491,3920 v1(5631,3920)
  Bottom Layer w10: U5.5 v1(5631,3920)
GPIO6: SW2.6 U5.6 | length 2080.9
  Inner1 w10: v1(3731.86,3967.8) 3816.8,3967.8 3918,4069 4863,4069 4947,3985 5383,3985 5498,3870 v1(5631,3870)
  Bottom Layer w10: U5.6 v1(5631,3870)
GPIO7: SW7.1 U5.7 | length 283
  Top Layer w10: SW7.1 5501.93,3984 v1(5503,3984)
  Bottom Layer w10: v1(5503,3984) 5503,3867 5548,3822 5571.58,3822 U5.7
GPIO8: SW5.1 U5.8 | length 557.4
  Top Layer w10: SW5.1 5292,4136 v1(5313,4115)
  Bottom Layer w10: v1(5313,4115) 5468,3960 5468,3853 5553,3768 5571.58,3768 U5.8
GPIO9: D3.2 U5.9 | length 1134.9
  Top Layer w10: D3.2 v1(4714,4004)
  Inner1 w10: v1(4714,4004) 4809,3909 5411,3909 5600,3720 v1(5631,3720)
  Bottom Layer w10: U5.9 v1(5631,3720)
GPIO10: Q3.1 R4.2 U5.10 | length 789.8
  Top Layer w10: Q3.1 4980,3732.32 R4.2 5030,3677.66 v1(5030,3630)
  Inner1 w10: v1(5030,3630) 5050,3650 v1(5465,3650)
  Bottom Layer w10: v1(5465,3650) 5485,3670 U5.10
GPIO11: Q5.1 R14.1 U5.12 | length 1155.8
  Top Layer w10: R14.1 4652.98,3838.66 Q5.1 4680.32,3866 v1(4720,3866)
  Inner1 w10: v1(4720,3866) 4720,3819 4976,3563 v1(5477,3563)
  Bottom Layer w10: v1(5477,3563) 5566.58,3563 U5.12
GPIO12: M1.11 U5.14 | length 1429.9
  Top Layer w10: v1(4462,3670) 4489,3697 4538,3697 4550,3685 4550,3604.6 M1.11
  Inner1 w10: v1(4462,3670) 4817,3670 5078,3409 5385,3409 v1(5440,3464)
  Bottom Layer w10: v1(5440,3464) 5567.58,3464 U5.14
GPIO42: M1.7 U5.25 | length 336.2
  Top Layer w10: M1.7 4659.99,3682.99 4679,3702 v1(4729,3702)
  Bottom Layer w10: v1(4729,3702) 4761,3670 U5.25
GPIO46: Q4.1 R12.1 U5.27 | length 1110.7
  Top Layer w10: v1(5363,3679) 5363,3715.66 R12.1 5478.33,3765.66 Q4.1
  Bottom Layer w10: U5.27 4954,3770 5205,3519 5205,3430 5228,3407 5339,3407 5363,3431 v1(5363,3679)
IMU_INT1: U7.4
IMU_INT2: U7.9
KEY_JS_BUTTON: SW2.2 U5.26 | length 2056.8
  Bottom Layer w10: v1(3573.25,4207.3) 3537,4171.05 3537,3960 3892,3605 4075,3605 4099,3629 4099,3830 4137,3868 4359,3868 4440,3787 4720,3787 4787,3720 U5.26
LCD_LEDK: M1.2 R15.2 | length 184.2
  Top Layer w15: M1.2 4797.79,3757.13 R15.2
RTC_INT: U6.3
SD_DET: CARD1.9
VBAT: C2.2 C3.2 C4.2 C8.2 D5.1 Q2.3 U2.1 U2.3 | length 1085.9
  Top Layer w10: 5069.74,3511 5070.37,3511.62 U2.3
  Top Layer w20: 5069.74,3511 5130,3511 5145.37,3526.37 U2.1
  Top Layer w30: Q2.3 5124.86,3931.86 C8.2 5188.76,3886 5249.76,3947 5342.24,3947 5373,3977.76 5373,4147 v2(5403,4177) ; C4.2 5156.81,3648.51 C3.2 C2.2 5156.81,3885.27 ; U2.1 C4.2@5145.37,3636.94
  other v2: 5387,4205 5419,4205
VBAT_IN: C11.2 C21.2 FPC1.2 Q1.3 U3.5 U6.8 | length 1738.1
  Top Layer w15: v1(4057,3642) 4208,3642 4220.56,3629.44 C21.2 4220.56,3552.44 4274,3499 U6.8
  Bottom Layer w15: v1(4057,3642) 4057,3994 4291,4228 4793,4228 4841,4180 v2(4986,4180)
  other v2: 5002,4152 5018,4180
VBUS: C1.2 C5.1 D5.2 R1.1 R18.1 U1.3 U3.4 U3.8 U5.13 | length 2055.5
  Top Layer w10: U3.4 4771.64,4213 4807.34,4248.7 4807.34,4386.35 4822.29,4386.35 ; R18.1 R1.1 4822.66,4386.72 4822.29,4386.35 ; U3.8 4974,4363 4950.65,4386.35 4822.29,4386.35
  Bottom Layer w30: v2(4734,4151) 4756,4151 4827,4080 5255,4080 ; D5.2 5255,4270.61 5255,4080 ; U5.13 5460,3520 5417,3563 5417,3918 5255,4080
  other v2: 4718,4179 4750,4179
VDD3V3: BUZZER1.1 C7.2 C9.2 C10.2 C20.2 C22.2 C23.2 CARD1.4 D6.1 M1.3 M1.4 R8.2 R9.2 R10.2 R11.2 R16.2 R17.2 U2.5 U5.28 U7.5 U7.8 U7.12 | length 4105.1
  Top Layer w10: C22.2 3660.38,3740.07 ; 3685,3740.13 3685,3801 3697.68,3813.68 U7.5 ; 3719,3673 3684.38,3673 3660.38,3697 3660.38,3740.07 ; U7.8 3660.38,3740.07 ; U7.12 3843.7,3774.3 3870,3748 3870,3713
  Top Layer w15: 3719,3673 3830,3673 3870,3713 4041,3713 ; R9.2 4059.4,3694.6 4041,3713 ; CARD1.4 4230.35,3912 4215.35,3927 4080,3927 4041,3888 4041,3713
  Top Layer w20: R9.2 R10.2 R11.2 R8.2 4379.6,3694.6 v1(4505,3820) ; 4755.88,3530.12 4770.56,3515.44 C23.2 4980,3471 5023.66,3427.34 R17.2 ; R16.2 R17.2 ; C7.2 5129.63,3366 R17.2 ; v2(5302,3481) 5323,3502 5509.9,3502 ; BUZZER1.1 5509.9,3502 ; C20.2 5563.45,3535.22 5563.22,3535.22 ; D6.1 5603,3575 5563.22,3535.22 ; 5509.9,3502 5530,3502 5563.22,3535.22
  Top Layer w30: 4755.88,3530.12 4755.88,3652 ; C7.2 C7.2@5144.37,3380.74 ; U2.5 C7.2@5144.37,3380.74 ; C10.2 C9.2 5144.73,3380.37 C7.2@5144.37,3380.74
  Bottom Layer w20: v1(4505,3820) U5.28
  Bottom Layer w30: U5.28 4980,3820 5270,3530 v2(5270,3481)
  other v2: 5286,3453
pads on no net: CARD1.1 CARD1.8 SW2.7 U2.4 U6.7 U7.2 U7.3 U7.10 U7.11

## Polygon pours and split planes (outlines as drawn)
VBAT_IN on Bottom Layer (solid, remove dead copper, pour order 10): 5030,4314.11 5030,4220 5009,4199 4968,4199 4968,4137 5035.6,4137 5093.12,4194.52 5093.12,4314.11
VBAT_IN on Top Layer (solid, remove dead copper, pour order 2): 4965.71,4228.1 4965.71,4194.65 4942,4170.94 4942,4123 4998,4123 5077.88,4202.88 5077.88,4228.1
VBUS on Top Layer (solid, remove dead copper, pour order 4): 4657.05,4221.44 4657.05,4122.35 4797,4122.35 4797,4200.5 4776.06,4221.44
VBUS on Bottom Layer (solid, remove dead copper, pour order 16): 4703,4195 4766,4195 4766,4135 4703,4135
VBAT on Bottom Layer (solid, remove dead copper, pour order 18): 5372,4306 5372,4162 5434,4162 5434,4306
VBAT on Top Layer (solid, remove dead copper, pour order 10): 5372,4162 5434,4162 5434,4221 5372,4221
VDD3V3 on Top Layer (solid, remove dead copper, pour order 12): 5231,3470 5231,3438 5294,3438 5317,3461 5317,3496 5257,3496
VDD3V3 on Bottom Layer (solid, remove dead copper, pour order 24): 5253.59,3499 5253.59,3437 5320,3437 5320,3499
GND on Top Layer (solid, remove dead copper, pour order 16): 3246,4668 5959,4668 5959,3000 3246,3000
GND on Bottom Layer (solid, remove dead copper, pour order 28): 3167,4769 5987,4769 5987,3032 3167,3032
GND on Inner1 (solid, remove dead copper): 3115,4819 6051,4819 6051,3093 3115,3093
GND on Inner2 (solid, remove dead copper): 3000,4956 6139,4956 6139,3146 3000,3146

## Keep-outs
Board Outline Layer:
  the board outline again, w10

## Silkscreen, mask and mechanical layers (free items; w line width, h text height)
Top Silkscreen Layer:
  text "JLCJLCJLCJLC" at 3981,4085 h60
Bottom Silkscreen Layer:
  lines w10: 3576.26,3256.9 3576.26,4359.26 4836.1,4359.26 4836.1,3256.9 3576.26,3256.9
Document Layer:
  circle w10: c3673.31,4109 r236.22
  circle w10: c5449.81,4266.48 r78.74
  circle w10: c5607.29,4103 r78.74
  circle w10: c5292.33,4109 r78.74
  circle w10: c5449.81,3945.52 r78.74
  circle w10: c5386,3508 r159
  lines w10: 3361,4292.39 3361,4310.32 3470.44,4419.77 ; 3361.74,3588.44 3489,3337 3734,3200 4331,3175 ; 4561.56,3266.65 4561.56,4495 ; 4561.56,3495 4561.56,4439.88 ; 5653.56,4419.77 5763,4310.32 5763,4292.39 ; 5762.26,3588.44 5635,3337 5390,3200 4793,3175 ; 4331,3175 4112.99,3119 3553,3119 3361,3311 3361,4382.05 4010.88,4606 4562,4606 5113.12,4606 5763,4382.05 5763,3311 5571,3119 5011.01,3119 4793,3175 ; 4331,3175 4562,3175 4793,3175 ; 3655.22,3531.67 ccw(c3693.3,3569.75) 3731.37,3531.67 3791.8,3592.1 ccw(c3753.72,3630.17) 3791.8,3668.25 ccw(c3753.72,3630.17) 3715.65,3668.25 3655.22,3607.82 ccw(c3693.3,3569.75) 3655.22,3531.67 ; 3728.71,3357.71 ccw(c3766.79,3395.79) 3804.86,3357.71 3865.29,3418.14 ccw(c3827.21,3456.21) 3865.29,3494.29 ccw(c3827.21,3456.21) 3789.14,3494.29 3728.71,3433.86 ccw(c3766.79,3395.79) 3728.71,3357.71 ; 4043.84,3302.09 5079.28,3302.09 5079.28,4459.57 4043.84,4459.57 4043.84,3302.09 ; 4098.84,3480.83 5020.1,3480.83 5020.1,4402.09 4098.84,4402.09 4098.84,3480.83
